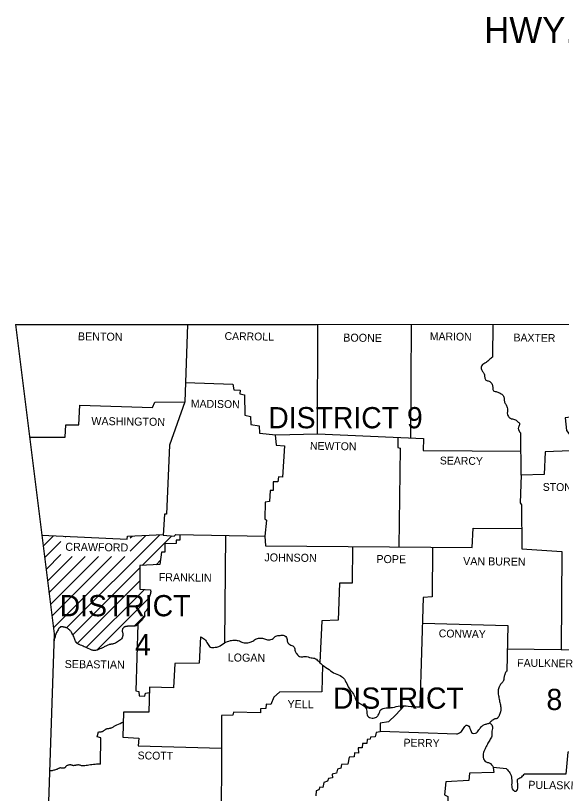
# Model space of a CAD drawing. Extents: x 6028666 to 6031787, y 5366484 to 5368484.
# Drawn here: x 6031108.5 to 6031401.8, y 5368029.7 to 5368447.7 of the extents above; entities that cross this region are included whole.
import ezdxf

# ---------------------------------------------------------------- set-up
doc = ezdxf.new("R2010")
doc.units = 0
for name, color, linetype in [('2', 7, 'Continuous'), ('Level 1', 7, 'Continuous'), ('R_Border', 7, 'Continuous')]:
    doc.layers.add(name, color=color, linetype=linetype)

msp = doc.modelspace()

# ---------------------------------------------------------------- linework, layer by layer
at = {"layer": '2'}
for points in [[(6031108.45, 5368281.69), (6031270.15, 5368281.59), (6031412.05, 5368281.89), (6031579.45, 5368284.49), (6031657.05, 5368286.29)], [(6031108.45, 5368281.69), (6031129.15, 5368115.5), (6031120.15, 5367844.2)], [(6031200.77, 5368281.63), (6031199.35, 5368240.09)], [(6031199.71, 5368250.52), (6031225.15, 5368249.69), (6031225.75, 5368246.49), (6031229.15, 5368246.39), (6031229.05, 5368244.39), (6031231.45, 5368243.79), (6031231.65, 5368232.89), (6031234.75, 5368232.19), (6031234.95, 5368227.89), (6031239.35, 5368227.29), (6031239.55, 5368223.29), (6031248.25, 5368222.39), (6031270.65, 5368222.89), (6031270.86, 5368281.59)], [(6031320.96, 5368281.7), (6031320.65, 5368220.79)], [(6031364.96, 5368281.79), (6031364.75, 5368264.19)], [(6031412.05, 5368281.89), (6031412.25, 5368257.49), (6031410.55, 5368257.39), (6031410.85, 5368232.49), (6031403.85, 5368231.49), (6031404.45, 5368224.79), (6031406.85, 5368221.69), (6031406.65, 5368213.79), (6031393.05, 5368213.29), (6031392.55, 5368201.09), (6031380.15, 5368200.69), (6031379.55, 5368185.89), (6031380.25, 5368184.69), (6031380.55, 5368161.09), (6031401.95, 5368159.69), (6031401.65, 5368107), (6031418.65, 5368106.5), (6031418.65, 5368052.9), (6031405.25, 5368051.9), (6031404.25, 5368040.1), (6031381.75, 5368040)], [(6031115.99, 5368221.2), (6031135.05, 5368221.09), (6031135.55, 5368227.69), (6031142.45, 5368227.69), (6031143.05, 5368238.39), (6031182.05, 5368236.99), (6031183.25, 5368239.99), (6031199.35, 5368240.09), (6031191.25, 5368216.89), (6031189.65, 5368179.79), (6031188.45, 5368179.69), (6031187.85, 5368168.49), (6031193.75, 5368167.99), (6031194.65, 5368168.89), (6031242.35, 5368167.99), (6031242.85, 5368162.69)], [(6031380.15, 5368200.69), (6031380.05, 5368223.19)], [(6031248.04, 5368222.42), (6031248.45, 5368216.79), (6031253.05, 5368216.49), (6031251.85, 5368199.69), (6031249.75, 5368199.79), (6031249.35, 5368197.09), (6031246.95, 5368197.09), (6031246.85, 5368192.49), (6031245.35, 5368192.39), (6031244.85, 5368186.49), (6031242.65, 5368186.19), (6031242.35, 5368177.19), (6031243.35, 5368176.49), (6031242.35, 5368167.99)], [(6031270.65, 5368222.89), (6031327.65, 5368220.49), (6031327.55, 5368213.99), (6031380.1, 5368213.59)], [(6031313.96, 5368221.07), (6031313.85, 5368215.59), (6031315.15, 5368215.29), (6031314.35, 5368162.12)], [(6031122.56, 5368168.41), (6031168.45, 5368166.29), (6031168.65, 5368167.89), (6031187.87, 5368168.8)], [(6031196.65, 5368168.86), (6031196.65, 5368165.79), (6031194.75, 5368165.79), (6031194.85, 5368163.99), (6031188.75, 5368163.89), (6031188.65, 5368159.39), (6031186.95, 5368159.39), (6031186.05, 5368152.7), (6031175.25, 5368152.2), (6031175.15, 5368139.5), (6031180.95, 5368139.1)], [(6031242.85, 5368162.69), (6031353.85, 5368161.79), (6031354.35, 5368172.29), (6031380.41, 5368171.99)], [(6031221.35, 5368168.39), (6031220.65, 5368110.7)], [(6031289.49, 5368162.32), (6031289.38, 5368142.73), (6031282.48, 5368142.63), (6031281.88, 5368122.73), (6031273.08, 5368122.43), (6031271.99, 5368099.99)], [(6031332.56, 5368161.97), (6031332.35, 5368135.4), (6031327.55, 5368135), (6031325.65, 5368076.2)], [(6031174.19, 5368120.57), (6031173.15, 5368084.9), (6031174.65, 5368084.5), (6031174.95, 5368082.1), (6031177.95, 5368081.9), (6031178.25, 5368083.6), (6031180.37, 5368083.95)], [(6031327.1, 5368121.1), (6031373.05, 5368120), (6031372.45, 5368095.3)], [(6031207.75, 5368113.9), (6031207.05, 5368099.6), (6031194.05, 5368099.5), (6031193.35, 5368086.5), (6031180.45, 5368086.8), (6031180.05, 5368073.4), (6031166.55, 5368073.3), (6031166.15, 5368059.9), (6031174.65, 5368059.4), (6031174.35, 5368055.3), (6031219.09, 5368054.06)], [(6031372.55, 5368107.4), (6031401.65, 5368107)], [(6031273.45, 5368098.6), (6031273.05, 5368084.2), (6031250.25, 5368084.1), (6031247.25, 5368081.5), (6031245.55, 5368077.5), (6031243.05, 5368077.7), (6031242.95, 5368075.4), (6031240.05, 5368075.1), (6031240.15, 5368073), (6031225.65, 5368073.4), (6031225.15, 5368071.8), (6031219.15, 5368071.6), (6031219.09, 5368054.06)], [(6031317.21, 5368076.73), (6031312.75, 5368071.9), (6031308.85, 5368068.2), (6031304.35, 5368067.5), (6031304.35, 5368062.8), (6031302.15, 5368062.5), (6031301.75, 5368060.1), (6031299.25, 5368059.9), (6031299.05, 5368058.8), (6031297.35, 5368058.7), (6031297.25, 5368056.6), (6031294.85, 5368056.5), (6031294.65, 5368054.1), (6031292.65, 5368054.1), (6031292.75, 5368051.3), (6031290.55, 5368051.5), (6031290.45, 5368049.3), (6031287.75, 5368049.1), (6031286.95, 5368045.5), (6031283.55, 5368045.2), (6031283.25, 5368043.2), (6031281.45, 5368042.7), (6031280.95, 5368040.6), (6031278.65, 5368040.1), (6031278.85, 5368038), (6031276.55, 5368037.8), (6031276.15, 5368036.2), (6031274.05, 5368035.6), (6031273.55, 5368032.9), (6031271.95, 5368033), (6031271.45, 5368031.6), (6031269.95, 5368031.1), (6031269.85, 5368028.4)], [(6031154.05, 5368045.4), (6031154.35, 5368059.5), (6031152.35, 5368060.1), (6031152.95, 5368062.8)], [(6031345.65, 5368061.6), (6031304.35, 5368062.9)], [(6031219.09, 5368054.06), (6031218.95, 5368013.1), (6031213.95, 5368013), (6031214.35, 5368010), (6031209.55, 5368010.1), (6031209.45, 5368007.9), (6031204.75, 5368007.9), (6031204.85, 5368006.3), (6031197.85, 5368006.1), (6031197.75, 5368000), (6031190.95, 5368000.6), (6031189.85, 5367951.4), (6031151.35, 5367951.5), (6031150.45, 5367940.1), (6031151.85, 5367939.1), (6031151.75, 5367926.3), (6031122.92, 5367927.57)], [(6031372.35, 5368042.9), (6031365.15, 5368043.7), (6031365.45, 5368041), (6031352.35, 5368040.5), (6031351.95, 5368036.6), (6031339.65, 5368035.9), (6031338.95, 5368028.9), (6031340.75, 5368028), (6031340.75, 5368023.4)]]:
    msp.add_lwpolyline(points, dxfattribs=at)
for points in [[(6031364.75, 5368264.19), (6031362.95, 5368262.69), (6031361.35, 5368261.29), (6031358.95, 5368259.59), (6031358.65, 5368257.99), (6031359.45, 5368256.39), (6031360.25, 5368255.09), (6031360.55, 5368253.29), (6031361.25, 5368251.79), (6031362.95, 5368251.19), (6031364.35, 5368249.89), (6031364.85, 5368248.09), (6031365.05, 5368246.39), (6031366.65, 5368245.59), (6031368.45, 5368244.99), (6031370.15, 5368243.79), (6031370.95, 5368242.29), (6031371.15, 5368240.39), (6031371.85, 5368238.89), (6031372.65, 5368237.09), (6031372.85, 5368235.59), (6031372.65, 5368234.09), (6031373.05, 5368232.69), (6031374.35, 5368231.29), (6031376.65, 5368230.59), (6031378.25, 5368229.59), (6031379.35, 5368228.19), (6031378.65, 5368226.49), (6031378.75, 5368224.99), (6031380.05, 5368223.19)], [(6031180.95, 5368139.1), (6031181.04, 5368138.57), (6031181.08, 5368138.04), (6031180.95, 5368137), (6031180.77, 5368136.44), (6031180.56, 5368135.9), (6031180.35, 5368135.35), (6031180.15, 5368134.8), (6031179.65, 5368132.9), (6031179.65, 5368132.28), (6031179.81, 5368131.65), (6031179.96, 5368131.02), (6031179.99, 5368130.71), (6031179.95, 5368130.4), (6031179.58, 5368129.37), (6031179.05, 5368128.4), (6031178.75, 5368127.98), (6031178.39, 5368127.59), (6031178.04, 5368127.21), (6031177.75, 5368126.8), (6031177.67, 5368126.32), (6031177.76, 5368125.8), (6031177.85, 5368125.27), (6031177.75, 5368124.8), (6031177.59, 5368124.52), (6031177.43, 5368124.24), (6031177.07, 5368123.7), (6031176.68, 5368123.18), (6031176.25, 5368122.7), (6031174.65, 5368121.1), (6031174.02, 5368120.38), (6031173.67, 5368120.05), (6031173.47, 5368119.91), (6031173.37, 5368119.85), (6031173.25, 5368119.8), (6031172.64, 5368119.63), (6031172.01, 5368119.59), (6031171.38, 5368119.6), (6031171.07, 5368119.6), (6031170.75, 5368119.6), (6031169.7, 5368119.55), (6031168.65, 5368119.5), (6031168.11, 5368119.44), (6031167.58, 5368119.33), (6031167.06, 5368119.12), (6031166.81, 5368118.98), (6031166.55, 5368118.8), (6031166.22, 5368118.47), (6031165.99, 5368118.1), (6031165.84, 5368117.71), (6031165.75, 5368117.3), (6031165.78, 5368116.72), (6031165.95, 5368116.15), (6031166.12, 5368115.57), (6031166.15, 5368115), (6031166.06, 5368114.43), (6031165.92, 5368113.87), (6031165.35, 5368112.8), (6031164.37, 5368111.82), (6031163.25, 5368111.1), (6031162.13, 5368110.48), (6031160.95, 5368110), (6031160.36, 5368109.87), (6031159.74, 5368109.82), (6031159.13, 5368109.76), (6031158.55, 5368109.6), (6031157.72, 5368109.21), (6031156.9, 5368108.81), (6031156.08, 5368108.39), (6031155.25, 5368108), (6031152.25, 5368106.7), (6031151.47, 5368106.51), (6031150.65, 5368106.5), (6031149.83, 5368106.64), (6031149.05, 5368106.9), (6031146.05, 5368108.2), (6031143.35, 5368109.4), (6031142.79, 5368109.63), (6031142.23, 5368109.88), (6031141.71, 5368110.18), (6031141.47, 5368110.37), (6031141.36, 5368110.48), (6031141.25, 5368110.6), (6031140.69, 5368111.46), (6031140.29, 5368112.4), (6031139.95, 5368113.36), (6031139.77, 5368113.84), (6031139.55, 5368114.3), (6031139.02, 5368115.3), (6031138.45, 5368116.3), (6031138.07, 5368116.86), (6031137.63, 5368117.38), (6031137.13, 5368117.85), (6031136.85, 5368118.08), (6031136.55, 5368118.3), (6031136, 5368118.61), (6031135.42, 5368118.83), (6031134.84, 5368118.98), (6031134.25, 5368119.1), (6031133.77, 5368119.19), (6031133.27, 5368119.24), (6031132.78, 5368119.17), (6031132.56, 5368119.07), (6031132.45, 5368118.99), (6031132.35, 5368118.9), (6031131.01, 5368117.11), (6031130.13, 5368115.25), (6031129.54, 5368113.34), (6031129.02, 5368111.4)], [(6031220.65, 5368110.7), (6031223.95, 5368111.8), (6031226.35, 5368112), (6031228.75, 5368111.6), (6031231.25, 5368110.6), (6031233.95, 5368110.8), (6031235.95, 5368111.5), (6031237.95, 5368112.8), (6031240.15, 5368113.2), (6031242.25, 5368112.8), (6031244.45, 5368112.2), (6031246.85, 5368112.9), (6031248.25, 5368114.2), (6031250.65, 5368114.6), (6031252.75, 5368114.6), (6031254.25, 5368112.9), (6031254.55, 5368111.1), (6031256.45, 5368109.4), (6031258.15, 5368108.3), (6031258.65, 5368106.2), (6031259.55, 5368104.7), (6031260.45, 5368103.7), (6031261.75, 5368103.1), (6031263.95, 5368103.3), (6031267.35, 5368102.6), (6031269.55, 5368102.1), (6031271.55, 5368100.4), (6031273.45, 5368098.6)], [(6031207.75, 5368113.9), (6031209.95, 5368112.5), (6031211.65, 5368110.2), (6031213.15, 5368108.3), (6031215.65, 5368108.2), (6031217.65, 5368108.6), (6031220.65, 5368110.7)], [(6031273.45, 5368098.6), (6031276.95, 5368096.2), (6031280.25, 5368094.1), (6031283.65, 5368092.6), (6031285.55, 5368090.4), (6031287.25, 5368087), (6031288.65, 5368084.9), (6031290.45, 5368082.3), (6031291.75, 5368079.4), (6031293.85, 5368077.8), (6031296.05, 5368076.4), (6031297.15, 5368073.9), (6031297.65, 5368071.4), (6031300.05, 5368070.2), (6031302.35, 5368070.7), (6031303.65, 5368072.2), (6031304.85, 5368074.8), (6031307.55, 5368075.6), (6031311.05, 5368075.9), (6031315.05, 5368076.8), (6031319.45, 5368076.6), (6031325.65, 5368076.2)], [(6031372.45, 5368095.3), (6031372.31, 5368095.34), (6031372.15, 5368095.21), (6031371.81, 5368094.6), (6031371.46, 5368093.77), (6031371.3, 5368093.36), (6031371.15, 5368093), (6031370.94, 5368092.24), (6031370.86, 5368091.47), (6031370.78, 5368090.71), (6031370.69, 5368090.35), (6031370.55, 5368090), (6031370.21, 5368089.49), (6031369.78, 5368089.04), (6031369.33, 5368088.59), (6031368.95, 5368088.1), (6031368.65, 5368087.57), (6031368.36, 5368087.03), (6031367.95, 5368085.9), (6031367.88, 5368085.54), (6031367.82, 5368085.17), (6031367.76, 5368084.44), (6031367.76, 5368083.72), (6031367.85, 5368083), (6031368.35, 5368080.4), (6031368.85, 5368077.9), (6031369.07, 5368076.75), (6031369.16, 5368076.17), (6031369.25, 5368075.6), (6031369.28, 5368074.87), (6031369.16, 5368074.15), (6031368.97, 5368073.42), (6031368.86, 5368073.06), (6031368.75, 5368072.7), (6031368.53, 5368072.02), (6031368.26, 5368071.37), (6031367.91, 5368070.76), (6031367.7, 5368070.47), (6031367.58, 5368070.33), (6031367.45, 5368070.2), (6031367, 5368069.92), (6031366.47, 5368069.8), (6031365.93, 5368069.7), (6031365.45, 5368069.5), (6031365.12, 5368069.26), (6031364.79, 5368069.03), (6031364.14, 5368068.54), (6031363.54, 5368067.99), (6031363.02, 5368067.38)], [(6031152.95, 5368062.8), (6031153.5, 5368062.72), (6031154.06, 5368062.73), (6031154.89, 5368062.9), (6031155.02, 5368062.95), (6031155.15, 5368063), (6031155.44, 5368063.14), (6031155.7, 5368063.31), (6031156.21, 5368063.71), (6031156.71, 5368064.1), (6031157.11, 5368064.34), (6031157.25, 5368064.4), (6031157.59, 5368064.5), (6031157.94, 5368064.57), (6031158.66, 5368064.66), (6031159.38, 5368064.77), (6031159.72, 5368064.87), (6031160.05, 5368065), (6031160.76, 5368065.36), (6031161.45, 5368065.75), (6031162.14, 5368066.14), (6031162.85, 5368066.5), (6031166.4, 5368068.12)], [(6031345.65, 5368061.6), (6031348.15, 5368063), (6031349.45, 5368065.1), (6031351.05, 5368066.4), (6031352.65, 5368064.6), (6031354.05, 5368062), (6031355.55, 5368062), (6031357.45, 5368063.8), (6031358.65, 5368065.4), (6031360.15, 5368066.6), (6031361.75, 5368067.1), (6031363.45, 5368067.3), (6031364.75, 5368065.4), (6031364.35, 5368062.4), (6031364.35, 5368060.4), (6031363.25, 5368058.3), (6031362.05, 5368056.1), (6031360.75, 5368053.6), (6031359.75, 5368050.9), (6031359.95, 5368048.3), (6031361.35, 5368046.6), (6031362.95, 5368046.1), (6031365.38, 5368043.67)], [(6031154.05, 5368045.4), (6031153.33, 5368045.41), (6031152.6, 5368045.4), (6031151.15, 5368045.3), (6031147.85, 5368044.9), (6031144.85, 5368044.5), (6031144.51, 5368044.49), (6031144.18, 5368044.53), (6031143.5, 5368044.7), (6031142.83, 5368044.89), (6031142.32, 5368044.99), (6031142.15, 5368045), (6031141.53, 5368044.95), (6031140.9, 5368044.81), (6031140.27, 5368044.66), (6031139.65, 5368044.6), (6031139.23, 5368044.66), (6031138.8, 5368044.79), (6031138.38, 5368044.93), (6031137.95, 5368045), (6031137.43, 5368044.97), (6031136.9, 5368044.87), (6031136.38, 5368044.71), (6031135.85, 5368044.5), (6031135.51, 5368044.24), (6031135.24, 5368043.88), (6031134.99, 5368043.53), (6031134.65, 5368043.3), (6031134.36, 5368043.23), (6031134.05, 5368043.22), (6031133.4, 5368043.29), (6031132.76, 5368043.37), (6031132.3, 5368043.34), (6031132.15, 5368043.3), (6031131.7, 5368043.11), (6031131.26, 5368042.89), (6031130.82, 5368042.67), (6031130.35, 5368042.5), (6031129.45, 5368042.24), (6031128.54, 5368042), (6031127.63, 5368041.82), (6031126.7, 5368041.68)], [(6031372.35, 5368042.9), (6031374.05, 5368040.7), (6031375.05, 5368037.7), (6031375.05, 5368034.3), (6031375.85, 5368031.5), (6031377.45, 5368030.9), (6031378.45, 5368033.3), (6031378.25, 5368035.7), (6031378.25, 5368037.1), (6031379.95, 5368038.3), (6031381.75, 5368040)]]:
    msp.add_spline(points, degree=3, dxfattribs=at)
at = {"layer": 'Level 1'}
for p, q in [((6031135.87, 5368118.66), (6031185.92, 5368168.71)), ((6031123.28, 5368162.64), (6031128.77, 5368168.12)), ((6031124.06, 5368156.35), (6031132.81, 5368165.09)), ((6031135.16, 5368167.45), (6031135.52, 5368167.81)), ((6031142.23, 5368167.45), (6031142.28, 5368167.5)), ((6031170.07, 5368159.94), (6031178.5, 5368168.36)), ((6031170.07, 5368167.01), (6031171.07, 5368168.01)), ((6031176.53, 5368152.25), (6031192.39, 5368168.11)), ((6031124.85, 5368150.06), (6031132.81, 5368158.02)), ((6031125.63, 5368143.78), (6031138.87, 5368157.02)), ((6031126.41, 5368137.49), (6031145.94, 5368157.02)), ((6031127.2, 5368131.2), (6031153.01, 5368157.02)), ((6031127.98, 5368124.91), (6031160.08, 5368157.02)), ((6031128.76, 5368118.62), (6031167.16, 5368157.02)), ((6031183.95, 5368152.59), (6031186.37, 5368155.01)), ((6031139.22, 5368114.93), (6031175.24, 5368150.96)), ((6031141.61, 5368110.26), (6031175.19, 5368143.84)), ((6031146.44, 5368108.02), (6031177.74, 5368139.31)), ((6031152.15, 5368106.66), (6031180.09, 5368134.6)), ((6031172.15, 5368119.58), (6031177.85, 5368125.28))]:
    msp.add_line(p, q, dxfattribs=at)

# ---------------------------------------------------------------- texts
at = {"layer": '2'}
for s, height, rotation, p in [('BENTON', 4.301, 359.2527, (6031141.95, 5368273.19)), ('CARROLL', 4.2, 359.1481, (6031220.75, 5368273.39)), ('MARION', 4.2, 359.1854, (6031331.05, 5368273.29)), ('BOONE', 4.301, 359.4001, (6031284.55, 5368272.49)), ('BAXTER', 4.2, 359.256, (6031376.05, 5368272.59)), ('MADISON', 4.2, 359.0906, (6031202.65, 5368237.09)), ('WASHINGTON', 4.299, 359.232, (6031149.15, 5368227.69)), ('NEWTON', 4.2, 359.2717, (6031266.65, 5368214.39)), ('SEARCY', 4.199, 359.2527, (6031336.45, 5368206.49)), ('STONE', 4.199, 359.4001, (6031391.75, 5368192.29)), ('CRAWFORD', 4.299, 359.2771, (6031135.15, 5368160.09)), ('JOHNSON', 4.301, 359.3514, (6031242.15, 5368154.4)), ('POPE', 4.301, 359.6155, (6031302.35, 5368153.5)), ('VAN BUREN', 4.301, 359.3508, (6031348.95, 5368152.4)), ('FRANKLIN', 4.301, 359.1816, (6031185.35, 5368143.8)), ('CONWAY', 4.199, 359.0372, (6031335.85, 5368113.6)), ('LOGAN', 4.301, 359.3969, (6031222.45, 5368100.6)), ('FAULKNER', 4.2, 359.2486, (6031378.05, 5368097.8)), ('SEBASTIAN', 4.299, 359.2816, (6031134.85, 5368097.1)), ('YELL', 4.301, 359.1987, (6031254.55, 5368075.6)), ('PERRY', 4.2, 359.0858, (6031316.95, 5368054.9)), ('SCOTT', 4.2, 359.4063, (6031174.05, 5368048)), ('PULASKI', 4.301, 359.0531, (6031383.95, 5368032.2))]:
    msp.add_text(s, height=height, rotation=rotation, dxfattribs=at).set_placement(p)
for s, p in [('DISTRICT 9', (6031244.25, 5368225.89)), ('DISTRICT', (6031132.17, 5368124.88)), ('4', (6031172.67, 5368103.88)), ('DISTRICT', (6031279.05, 5368075.2)), ('8', (6031393.75, 5368074.5))]:
    msp.add_text(s, height=11.4, dxfattribs=at).set_placement(p)
at = {"layer": 'R_Border'}
msp.add_text('HWY. 59 REALIGNMENT (CRAWFORD CO.) (S)', height=14, dxfattribs=at).set_placement((6031360.27, 5368432.93))

doc.saveas('drawing.dxf')
